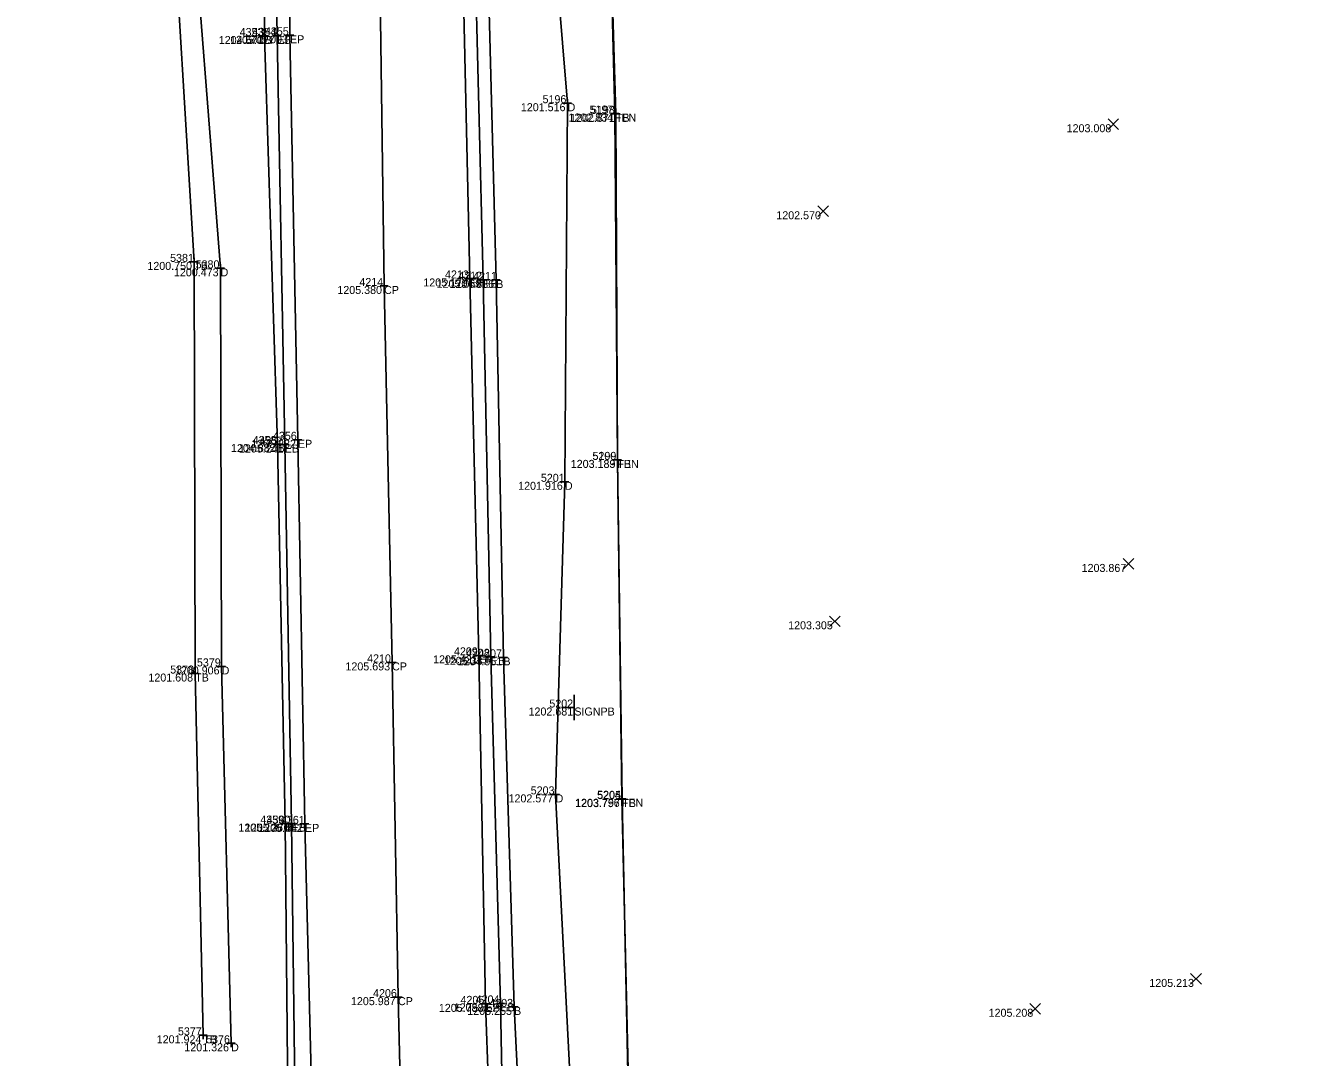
# Model space of a CAD drawing. Extents: x 2044996 to 2050343, y 455232 to 458054.
# Drawn here: x 2047583.1 to 2047743.9, y 457071.9 to 457200.9 of the extents above; entities that cross this region are included whole.
import ezdxf

# ---------------------------------------------------------------- set-up
doc = ezdxf.new("R2010")
doc.units = 0
for name, color, linetype in [('DR_X_Ditch', 7, 'Continuous'), ('DT_X_Contour_Minor', 7, 'Continuous'), ('DT_X_Contour_Text', 7, 'Continuous'), ('DT_X_Spot_Elev', 7, 'Continuous'), ('DT_X_Triangles', 7, 'Continuous'), ('DT_X_Void', 7, 'Continuous'), ('PV_X_COP', 7, 'Continuous'), ('PV_X_EOP', 7, 'Continuous'), ('PV_X_Shoulder_Aggregate', 7, 'Continuous'), ('RD_X_Fence', 7, 'Continuous'), ('SN_X_Public', 7, 'Continuous'), ('SV_X_Break_Lines', 7, 'Continuous'), ('SV_X_Top_of_Bank', 7, 'Continuous')]:
    doc.layers.add(name, color=color, linetype=linetype)

msp = doc.modelspace()

# ---------------------------------------------------------------- linework, layer by layer
at = {"layer": 'DR_X_Ditch'}
for points in [[(2047635.93, 457828.45), (2047636.46, 457778.33), (2047635.67, 457731.58), (2047635.87, 457688.92), (2047636.59, 457650.58), (2047637.14, 457615.31), (2047638.36, 457574.87), (2047638.82, 457526.07), (2047639.21, 457482.92), (2047639.9, 457443.66), (2047641.24, 457398.66), (2047642.28, 457344.51), (2047644.03, 457300.89), (2047646.18, 457262.24), (2047646.96, 457237.04), (2047650.76, 457191.22), (2047650.42, 457143.89), (2047649.26, 457104.81), (2047651.9, 457052.9), (2047656.34, 457022.85)], [(2047608.71, 457073.69), (2047607.53, 457120.81), (2047607.4, 457170.58), (2047603.33, 457222.06), (2047599.18, 457233.48)]]:
    msp.add_lwpolyline(points, dxfattribs=at)
at = {"layer": 'DT_X_Spot_Elev'}
for p, q in [((2047718.29, 457187.92), (2047719.62, 457189.25)), ((2047718.29, 457189.25), (2047719.62, 457187.92)), ((2047682.02, 457177.04), (2047683.35, 457178.37)), ((2047682.02, 457178.37), (2047683.35, 457177.04)), ((2047720.2, 457132.95), (2047721.53, 457134.29)), ((2047720.2, 457134.29), (2047721.53, 457132.95)), ((2047683.5, 457125.78), (2047684.83, 457127.11)), ((2047683.5, 457127.11), (2047684.83, 457125.78)), ((2047728.61, 457081.08), (2047729.95, 457082.41)), ((2047728.61, 457082.41), (2047729.95, 457081.08)), ((2047708.54, 457077.34), (2047709.87, 457078.68)), ((2047708.54, 457078.68), (2047709.87, 457077.34))]:
    msp.add_line(p, q, dxfattribs=at)
at = {"layer": 'DT_X_Void'}
for p, q in [((2047612.89, 457200.12), (2047612.89, 457199.12)), ((2047614.47, 457200.14), (2047614.47, 457199.14)), ((2047616.07, 457200.21), (2047616.07, 457199.21)), ((2047612.39, 457199.62), (2047613.39, 457199.62)), ((2047612.89, 457199.62), (2047612.89, 457199.62)), ((2047613.97, 457199.64), (2047614.97, 457199.64)), ((2047614.47, 457199.64), (2047614.47, 457199.64)), ((2047615.57, 457199.71), (2047616.57, 457199.71)), ((2047616.07, 457199.71), (2047616.07, 457199.71)), ((2047650.26, 457191.22), (2047651.26, 457191.22)), ((2047650.76, 457191.72), (2047650.76, 457190.72)), ((2047650.76, 457191.22), (2047650.76, 457191.22)), ((2047656.66, 457190.43), (2047656.66, 457189.43)), ((2047656.79, 457190.39), (2047656.79, 457189.39)), ((2047656.16, 457189.93), (2047657.16, 457189.93)), ((2047656.29, 457189.89), (2047657.29, 457189.89)), ((2047656.66, 457189.93), (2047656.66, 457189.93)), ((2047656.79, 457189.89), (2047656.79, 457189.89)), ((2047603.59, 457171.38), (2047604.59, 457171.38)), ((2047604.09, 457171.88), (2047604.09, 457170.88)), ((2047604.09, 457171.38), (2047604.09, 457171.38)), ((2047607.4, 457171.08), (2047607.4, 457170.08)), ((2047606.9, 457170.58), (2047607.9, 457170.58)), ((2047607.4, 457170.58), (2047607.4, 457170.58)), ((2047638.04, 457169.31), (2047639.04, 457169.31)), ((2047638.54, 457169.81), (2047638.54, 457168.81)), ((2047638.54, 457169.31), (2047638.54, 457169.31)), ((2047640.21, 457169.65), (2047640.21, 457168.65)), ((2047641.84, 457169.62), (2047641.84, 457168.62)), ((2047627.33, 457168.37), (2047628.33, 457168.37)), ((2047627.83, 457168.87), (2047627.83, 457167.87)), ((2047627.83, 457168.37), (2047627.83, 457168.37)), ((2047639.71, 457169.15), (2047640.71, 457169.15)), ((2047640.21, 457169.15), (2047640.21, 457169.15)), ((2047641.34, 457169.12), (2047642.34, 457169.12)), ((2047641.84, 457169.12), (2047641.84, 457169.12)), ((2047614.03, 457148.61), (2047615.03, 457148.61)), ((2047614.53, 457149.11), (2047614.53, 457148.11)), ((2047614.53, 457148.61), (2047614.53, 457148.61)), ((2047614.91, 457148.55), (2047615.91, 457148.55)), ((2047615.41, 457149.05), (2047615.41, 457148.05)), ((2047615.41, 457148.55), (2047615.41, 457148.55)), ((2047616.56, 457149.14), (2047617.56, 457149.14)), ((2047617.06, 457149.64), (2047617.06, 457148.64)), ((2047617.06, 457149.14), (2047617.06, 457149.14)), ((2047656.98, 457147.13), (2047656.98, 457146.13)), ((2047656.98, 457147.12), (2047656.98, 457146.12)), ((2047656.48, 457146.63), (2047657.48, 457146.63)), ((2047656.48, 457146.62), (2047657.48, 457146.62)), ((2047656.98, 457146.63), (2047656.98, 457146.63)), ((2047656.98, 457146.62), (2047656.98, 457146.62)), ((2047649.92, 457143.89), (2047650.92, 457143.89)), ((2047650.42, 457144.39), (2047650.42, 457143.39)), ((2047650.42, 457143.89), (2047650.42, 457143.89)), ((2047639.66, 457122.69), (2047639.66, 457121.69)), ((2047607.53, 457121.31), (2047607.53, 457120.31)), ((2047628.33, 457121.31), (2047629.33, 457121.31)), ((2047628.83, 457121.81), (2047628.83, 457120.81)), ((2047628.83, 457121.31), (2047628.83, 457121.31)), ((2047639.16, 457122.19), (2047640.16, 457122.19)), ((2047639.66, 457122.19), (2047639.66, 457122.19)), ((2047640.68, 457122.01), (2047641.68, 457122.01)), ((2047641.18, 457122.51), (2047641.18, 457121.51)), ((2047641.18, 457122.01), (2047641.18, 457122.01)), ((2047642.24, 457121.94), (2047643.24, 457121.94)), ((2047642.74, 457122.44), (2047642.74, 457121.44)), ((2047642.74, 457121.94), (2047642.74, 457121.94)), ((2047603.72, 457119.92), (2047604.72, 457119.92)), ((2047604.22, 457120.42), (2047604.22, 457119.42)), ((2047604.22, 457119.92), (2047604.22, 457119.92)), ((2047607.03, 457120.81), (2047608.03, 457120.81)), ((2047607.53, 457120.81), (2047607.53, 457120.81)), ((2047649.26, 457105.31), (2047649.26, 457104.31)), ((2047648.76, 457104.81), (2047649.76, 457104.81)), ((2047649.26, 457104.81), (2047649.26, 457104.81)), ((2047657.03, 457104.26), (2047658.03, 457104.26)), ((2047657.09, 457104.22), (2047658.09, 457104.22)), ((2047657.53, 457104.76), (2047657.53, 457103.76)), ((2047657.53, 457104.26), (2047657.53, 457104.26)), ((2047657.59, 457104.72), (2047657.59, 457103.72)), ((2047657.59, 457104.22), (2047657.59, 457104.22)), ((2047615.46, 457101.66), (2047615.46, 457100.66)), ((2047614.96, 457101.16), (2047615.96, 457101.16)), ((2047615.46, 457101.16), (2047615.46, 457101.16)), ((2047615.77, 457101.15), (2047616.77, 457101.15)), ((2047616.27, 457101.65), (2047616.27, 457100.65)), ((2047616.27, 457101.15), (2047616.27, 457101.15)), ((2047617.44, 457101.12), (2047618.44, 457101.12)), ((2047617.94, 457101.62), (2047617.94, 457100.62)), ((2047617.94, 457101.12), (2047617.94, 457101.12)), ((2047629.07, 457079.46), (2047630.07, 457079.46)), ((2047629.57, 457079.96), (2047629.57, 457078.96)), ((2047629.57, 457079.46), (2047629.57, 457079.46)), ((2047642.36, 457079.18), (2047642.36, 457078.18)), ((2047640.01, 457078.62), (2047641.01, 457078.62)), ((2047640.51, 457079.12), (2047640.51, 457078.12)), ((2047640.51, 457078.62), (2047640.51, 457078.62)), ((2047641.86, 457078.68), (2047642.86, 457078.68)), ((2047642.36, 457078.68), (2047642.36, 457078.68)), ((2047643.57, 457078.24), (2047644.57, 457078.24)), ((2047644.07, 457078.74), (2047644.07, 457077.74)), ((2047644.07, 457078.24), (2047644.07, 457078.24)), ((2047604.73, 457074.69), (2047605.73, 457074.69)), ((2047605.23, 457075.19), (2047605.23, 457074.19)), ((2047605.23, 457074.69), (2047605.23, 457074.69)), ((2047608.21, 457073.69), (2047609.21, 457073.69)), ((2047608.71, 457074.19), (2047608.71, 457073.19)), ((2047608.71, 457073.69), (2047608.71, 457073.69))]:
    msp.add_line(p, q, dxfattribs=at)
at = {"layer": 'PV_X_COP'}
msp.add_lwpolyline([(2047630.7, 457032.77), (2047629.57, 457079.46), (2047628.83, 457121.31), (2047627.83, 457168.37), (2047627.23, 457213.89), (2047626.35, 457261.41), (2047625.27, 457313.88), (2047624.14, 457367.69), (2047623.14, 457414.96), (2047622.16, 457463.48), (2047621.21, 457510.6), (2047620.34, 457561.9), (2047619.47, 457614.83), (2047618.33, 457662.23), (2047617.51, 457713.13), (2047616.39, 457759.38), (2047615.44, 457807.27), (2047614.41, 457854.52), (2047614.29, 457881.56), (2047613.16, 457931.14), (2047612.06, 457984.05), (2047611.48, 458032.26), (2047610.91, 458052.26)], dxfattribs=at)
at = {"layer": 'PV_X_EOP'}
for p, q in [((2047615.24, 457249.19), (2047616.07, 457199.71)), ((2047638.54, 457169.31), (2047637.55, 457212.47)), ((2047616.07, 457199.71), (2047617.06, 457149.14)), ((2047639.66, 457122.19), (2047638.54, 457169.31)), ((2047617.06, 457149.14), (2047617.94, 457101.12)), ((2047640.51, 457078.62), (2047639.66, 457122.19)), ((2047617.94, 457101.12), (2047619.08, 457054.97)), ((2047642.21, 457033.05), (2047640.51, 457078.62))]:
    msp.add_line(p, q, dxfattribs=at)
at = {"layer": 'PV_X_Shoulder_Aggregate'}
for p, q in [((2047613.53, 457249.46), (2047614.47, 457199.64)), ((2047614.47, 457199.64), (2047615.41, 457148.55)), ((2047615.41, 457148.55), (2047616.27, 457101.15)), ((2047616.27, 457101.15), (2047616.84, 457054))]:
    msp.add_line(p, q, dxfattribs=at)
msp.add_lwpolyline([(2047765.41, 456957.6), (2047718.77, 456974.89), (2047683.47, 456987.55), (2047664.01, 456996.43), (2047655.41, 457004.2), (2047650.14, 457012.19), (2047644.76, 457024.2), (2047643.27, 457033.33), (2047642.36, 457078.68), (2047641.18, 457122.01), (2047640.21, 457169.15), (2047639.13, 457212.34), (2047637.97, 457261.48), (2047636.93, 457312.89), (2047635.93, 457367.47)], dxfattribs=at)
at = {"layer": 'RD_X_Fence'}
msp.add_lwpolyline([(2047648.14, 457619.76), (2047649.39, 457574.65), (2047649.98, 457529.13), (2047650.66, 457480.39), (2047651.7, 457447.16), (2047652.23, 457398.03), (2047653.85, 457346.51), (2047654.21, 457298.97), (2047654.82, 457261.49), (2047656.66, 457189.93), (2047656.98, 457146.63), (2047657.53, 457104.26), (2047658.63, 457057.97)], dxfattribs=at)
at = {"layer": 'SN_X_Public'}
for p, q in [((2047651.6, 457117.27), (2047651.6, 457114.07)), ((2047651.6, 457115.67), (2047650, 457115.67))]:
    msp.add_line(p, q, dxfattribs=at)
at = {"layer": 'SV_X_Break_Lines'}
for points in [[(2047609.61, 457393.11), (2047610.32, 457343.26), (2047611.06, 457296.5), (2047612.48, 457248.74), (2047612.89, 457199.62), (2047614.53, 457148.61), (2047615.46, 457101.16), (2047615.94, 457053.96), (2047615.5, 457044.29), (2047611.53, 457035.42), (2047600.94, 457028.5), (2047592.5, 457026.1), (2047589.23, 457026.31), (2047543.28, 457040.88), (2047500.59, 457056.09), (2047456.76, 457072.2), (2047414.82, 457088.31), (2047369.13, 457105.97), (2047320.74, 457125.37), (2047273.19, 457143.6), (2047227.37, 457161.69), (2047183.55, 457178.86)], [(2047766.63, 456959.74), (2047718.99, 456976.33), (2047684.01, 456989.24), (2047664.81, 456998.06), (2047657.38, 457005.81), (2047652.26, 457013.72), (2047648.31, 457024.57), (2047646.23, 457034.09), (2047644.07, 457078.24), (2047642.74, 457121.94), (2047641.84, 457169.12), (2047640.7, 457212.33), (2047639.26, 457261.64), (2047638.13, 457312.9), (2047637.8, 457367.1)]]:
    msp.add_lwpolyline(points, dxfattribs=at)
at = {"layer": 'SV_X_Top_of_Bank'}
for points in [[(2047640.57, 457829.63), (2047642.73, 457776.65), (2047644.22, 457735.31), (2047644.62, 457692.67), (2047644.93, 457653.27), (2047648.25, 457619.87), (2047649.32, 457574.48), (2047650.08, 457529.2), (2047650.6, 457480.31), (2047651.65, 457447.12), (2047652.29, 457398.02), (2047653.83, 457346.33), (2047654.34, 457298.99), (2047654.68, 457261.41), (2047656.79, 457189.89), (2047656.98, 457146.62), (2047657.59, 457104.22), (2047658.54, 457057.89), (2047659.73, 457026.44)], [(2047605.23, 457074.69), (2047604.22, 457119.92), (2047604.09, 457171.38), (2047601.07, 457221.53), (2047596.9, 457233.14)]]:
    msp.add_lwpolyline(points, dxfattribs=at)

# ---------------------------------------------------------------- texts
at = {"layer": 'DT_X_Contour_Minor'}
for s, p in [('1204.571', (2047607.17, 457198.62)), ('1205.027', (2047608.59, 457198.64)), ('1205.093', (2047610.25, 457198.71)), ('1201.516', (2047644.92, 457190.22)), ('1202.834', (2047650.86, 457188.93)), ('1202.871', (2047651.07, 457188.89)), ('1203.008', (2047713.12, 457187.59)), ('1202.570', (2047676.84, 457176.71)), ('1200.750', (2047598.25, 457170.38)), ('1200.473', (2047601.57, 457169.58)), ('1205.179', (2047632.73, 457168.31)), ('1205.380', (2047621.99, 457167.37)), ('1205.069', (2047634.39, 457168.15)), ('1204.836', (2047636, 457168.12)), ('1204.882', (2047608.7, 457147.61)), ('1205.241', (2047609.69, 457147.55)), ('1205.282', (2047611.23, 457148.14)), ('1203.183', (2047651.15, 457145.63)), ('1203.189', (2047651.16, 457145.62)), ('1201.916', (2047644.58, 457142.89)), ('1203.867', (2047714.99, 457132.62)), ('1203.305', (2047678.32, 457125.45)), ('1205.693', (2047623, 457120.31)), ('1205.421', (2047633.95, 457121.19)), ('1205.337', (2047635.3, 457121.01)), ('1204.951', (2047637.02, 457120.94)), ('1201.608', (2047598.38, 457118.92)), ('1200.906', (2047601.69, 457119.81)), ('1202.681', (2047645.88, 457114.67)), ('1202.577', (2047643.38, 457103.81)), ('1203.756', (2047651.69, 457103.26)), ('1203.797', (2047651.71, 457103.22)), ('1205.126', (2047609.62, 457100.16)), ('1205.370', (2047610.44, 457100.15)), ('1205.442', (2047612.1, 457100.12)), ('1205.213', (2047723.45, 457080.74)), ('1205.987', (2047623.69, 457078.46)), ('1205.788', (2047634.67, 457077.62)), ('1205.562', (2047636.53, 457077.68)), ('1205.255', (2047638.23, 457077.24)), ('1205.208', (2047703.37, 457077.01)), ('1201.924', (2047599.42, 457073.69)), ('1201.326', (2047602.87, 457072.69))]:
    msp.add_text(s, height=1, dxfattribs=at).set_placement(p)
at = {"layer": 'DT_X_Contour_Text'}
for s, p in [('B', (2047612.89, 457198.62)), ('EB', (2047614.47, 457198.64)), ('EP', (2047616.07, 457198.71)), ('D', (2047650.76, 457190.22)), ('FEN', (2047656.66, 457188.93)), ('TB', (2047656.79, 457188.89)), ('TB', (2047604.09, 457170.38)), ('D', (2047607.4, 457169.58)), ('EP', (2047638.54, 457168.31)), ('CP', (2047627.83, 457167.37)), ('EB', (2047640.21, 457168.15)), ('B', (2047641.84, 457168.12)), ('B', (2047614.53, 457147.61)), ('EB', (2047615.41, 457147.55)), ('EP', (2047617.06, 457148.14)), ('TB', (2047656.98, 457145.62)), ('FEN', (2047656.98, 457145.63)), ('D', (2047650.42, 457142.89)), ('CP', (2047628.83, 457120.31)), ('EP', (2047639.66, 457121.19)), ('EB', (2047641.18, 457121.01)), ('B', (2047642.74, 457120.94)), ('TB', (2047604.22, 457118.92)), ('D', (2047607.53, 457119.81)), ('SIGNPB', (2047651.6, 457114.67)), ('D', (2047649.26, 457103.81)), ('TB', (2047657.59, 457103.22)), ('FEN', (2047657.53, 457103.26)), ('B', (2047615.46, 457100.16)), ('EB', (2047616.27, 457100.15)), ('EP', (2047617.94, 457100.12)), ('CP', (2047629.57, 457078.46)), ('EP', (2047640.51, 457077.62)), ('EB', (2047642.36, 457077.68)), ('B', (2047644.07, 457077.24)), ('TB', (2047605.23, 457073.69)), ('D', (2047608.71, 457072.69))]:
    msp.add_text(s, height=1, dxfattribs=at).set_placement(p)
at = {"layer": 'DT_X_Triangles'}
for s, p in [('4353', (2047609.78, 457199.62)), ('4354', (2047611.38, 457199.64)), ('4355', (2047612.94, 457199.71)), ('5196', (2047647.63, 457191.22)), ('5197', (2047653.5, 457189.93)), ('5198', (2047653.67, 457189.89)), ('5381', (2047601.09, 457171.38)), ('5380', (2047604.28, 457170.58)), ('4214', (2047624.74, 457168.37)), ('4213', (2047635.44, 457169.31)), ('4212', (2047637.1, 457169.15)), ('4211', (2047638.95, 457169.12)), ('4356', (2047613.94, 457149.14)), ('4358', (2047611.41, 457148.61)), ('4357', (2047612.24, 457148.55)), ('5200', (2047653.86, 457146.63)), ('5199', (2047653.88, 457146.62)), ('5201', (2047647.42, 457143.89)), ('4209', (2047636.56, 457122.19)), ('4208', (2047638.06, 457122.01)), ('4207', (2047639.58, 457121.94)), ('5379', (2047604.44, 457120.81)), ('4210', (2047625.71, 457121.31)), ('5378', (2047601.1, 457119.92)), ('5202', (2047648.48, 457115.67)), ('5203', (2047646.15, 457104.81)), ('5204', (2047654.44, 457104.26)), ('5205', (2047654.46, 457104.22)), ('4359', (2047612.36, 457101.16)), ('4360', (2047613.15, 457101.15)), ('4361', (2047614.94, 457101.12)), ('4206', (2047626.45, 457079.46)), ('4205', (2047637.38, 457078.62)), ('4204', (2047639.27, 457078.68)), ('4203', (2047640.97, 457078.24)), ('5377', (2047602.07, 457074.69)), ('5376', (2047605.59, 457073.69))]:
    msp.add_text(s, height=1, dxfattribs=at).set_placement(p)

doc.saveas('drawing.dxf')
